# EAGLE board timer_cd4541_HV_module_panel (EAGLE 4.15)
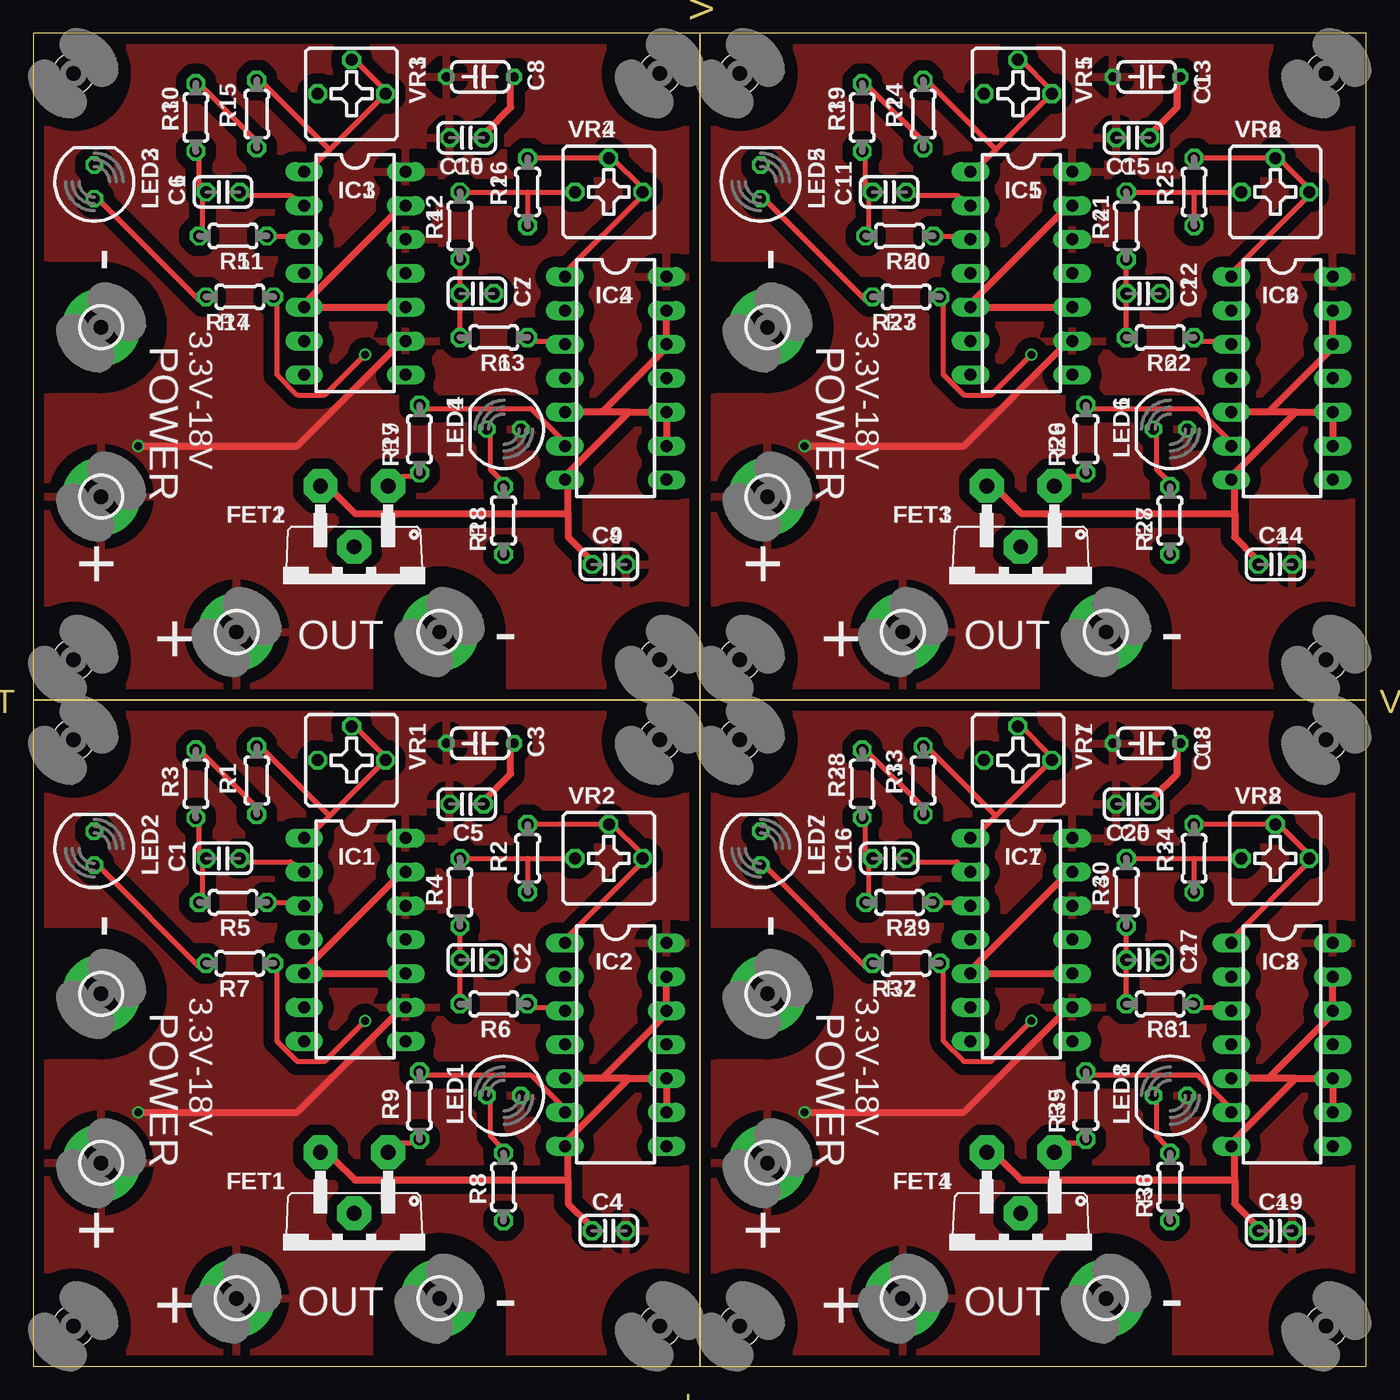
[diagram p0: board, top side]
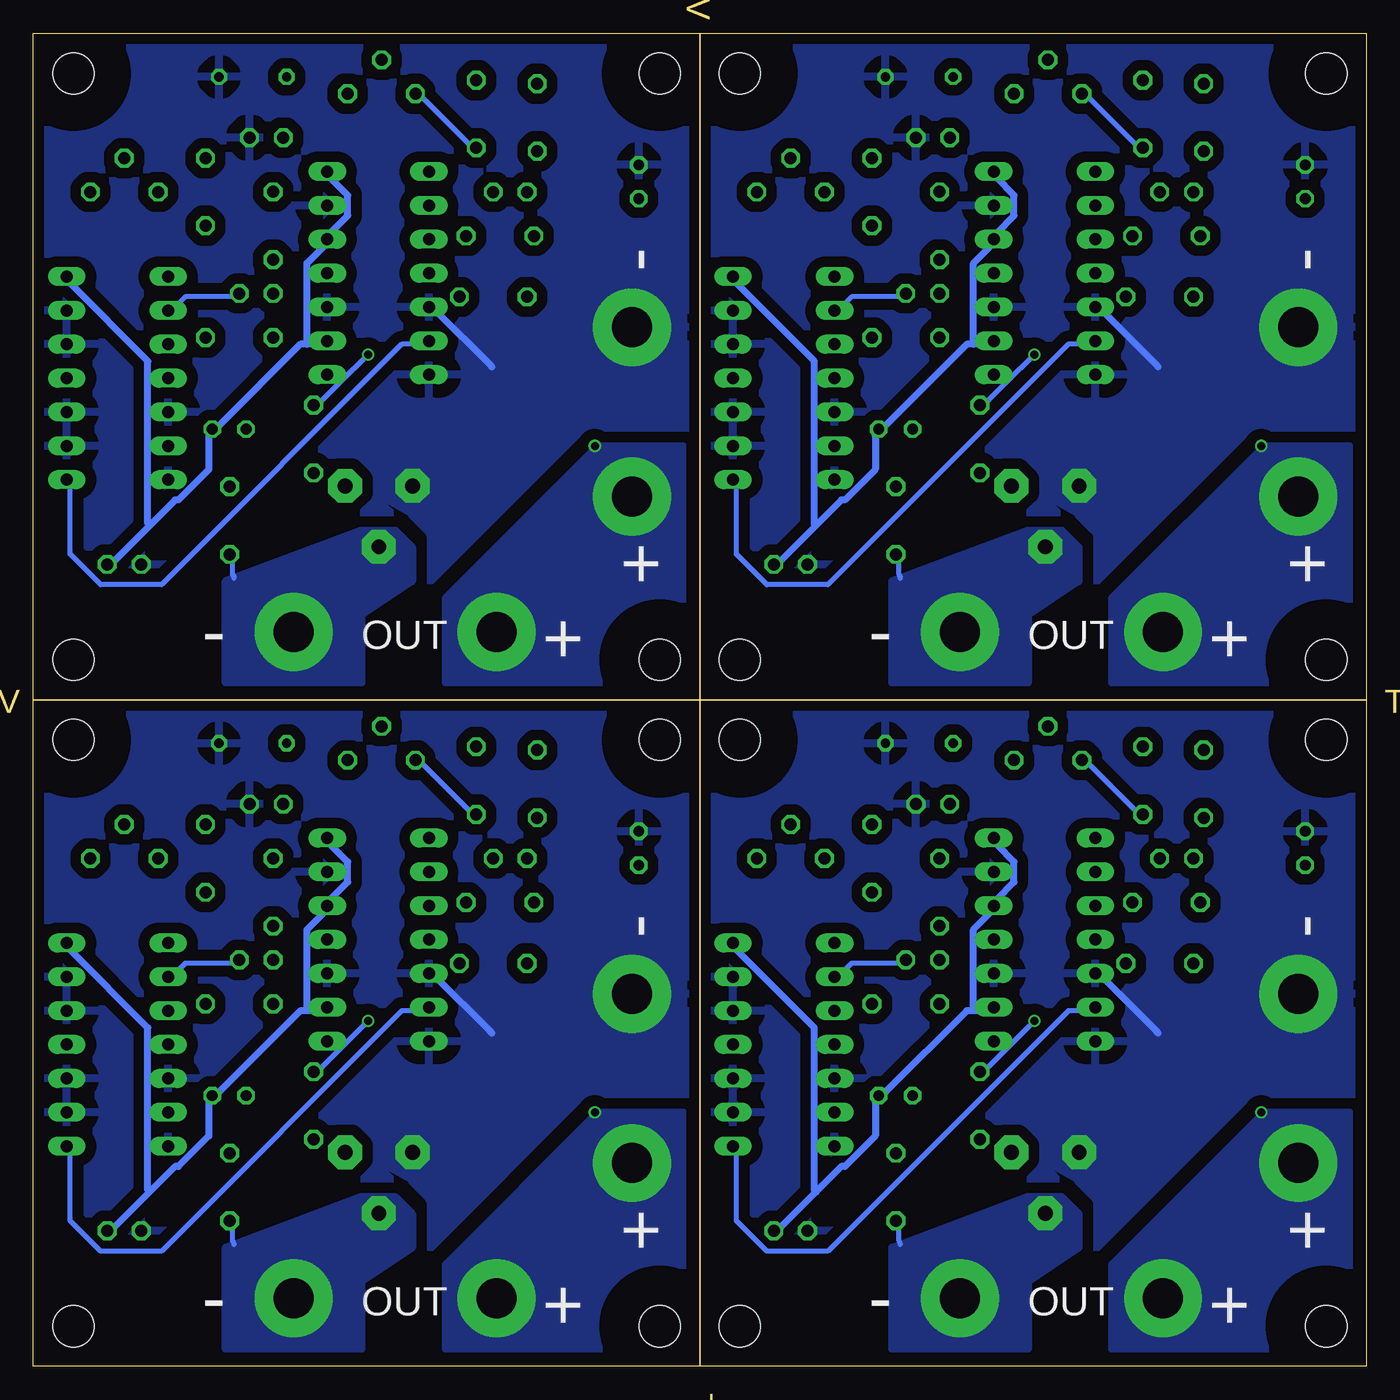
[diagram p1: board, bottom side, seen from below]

Size 100 x 100 mm. Coordinates in mm from the lower left corner, seen from the top.
Outline: 50,0 0,0 0,50
Outline: 50,0 50,50
Outline: 50,50 0,50
Outline: 0,50 50,50
Outline: 50,50 50,100
Outline: 50,100 0,100 0,50
Outline: 50,50 100,50
Outline: 100,50 100,100 50,100
Outline: 50,100 50,50
Outline: 50,0 100,0 100,50
Outline: 100,50 50,50
Outline: 50,50 50,0
Copper layers (1*16): Top 0.035mm / dielectric 1.5mm / Bottom 0.035mm
Design rules "FUSION_IIZUKA_STANDARD": minimum track width 6mil, minimum drill 0.6mm, track to track 8mil, track to pad 8mil, pad to pad 8mil, via to via 8mil, smd to smd 0mil, copper to edge 30mil, drill to drill 10mil, minimum pad ring 10mil, minimum via ring 6mil, stop-mask expansion 2mil, vias tented up to drill 100mil, thermal gap 40mil
Net classes: 0 default: width 0.381 mm, drill 0.406 mm; 1 power: width 0.508 mm, drill 0.508 mm
bKeepout: 20 lines
tRestrict: area 26.7,1 to 34.3,8.9; area 1,24.1 to 8.9,31.8; area 26.7,51 to 34.3,58.9; area 1,74.1 to 8.9,81.8; area 76.7,51 to 84.3,58.9; area 51,74.1 to 58.9,81.8; area 76.7,1 to 84.3,8.9; area 51,24.1 to 58.9,31.8
vRestrict: 1764 lines

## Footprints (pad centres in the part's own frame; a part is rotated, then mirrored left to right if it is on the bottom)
C025-024X044_OLMX = drill 0.9 octagon: 1 -1.27,0; 2 1.27,0
C050-024X044_OLMX = drill 0.7 octagon: 1 -2.54,0; 2 2.54,0
TO-220HV = drill 1.118 pad 2.54 octagon: 1 -2.54,-1.016; 2 0,3.556; 3 2.54,-1.016
3,0-PAD-NOLING = drill 3 pad 5.842 round: B3,0 0,0
3.1-HOLL = hole 3.1: 0,0
DIL14_OLMX = drill 0.9 long: 1 -7.62,-3.81; 2 -5.08,-3.81; 3 -2.54,-3.81; 4 0,-3.81; 5 2.54,-3.81; 6 5.08,-3.81; 7 7.62,-3.81; 8 7.62,3.81; 9 5.08,3.81; 10 2.54,3.81; 11 0,3.81; 12 -2.54,3.81; 13 -5.08,3.81; 14 -7.62,3.81
LED5MM_OLMX = drill 0.8 octagon: A -1.27,0; K 1.27,0
0204/5_OLMX = drill 0.9 octagon: 1 -2.54,0; 2 2.54,0
B25P_OLMX = drill 0.9 octagon: A -2.54,0; E 2.54,0; S 0,2.54

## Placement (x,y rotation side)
C1  1000pF(102)  [C025-024X044_OLMX]  14.22,38.1 0 top
C2  0.01uF(103)  [C025-024X044_OLMX]  33.27,30.48 0 top
C3  10uF  [C050-024X044_OLMX]  33.53,46.74 180 top
C4  0.1uF  [C025-024X044_OLMX]  43.18,10.16 0 top
C5  0.1uF  [C025-024X044_OLMX]  32.51,42.16 180 top
C6  1000pF(102)  [C025-024X044_OLMX]  14.22,88.1 0 top
C7  0.01uF(103)  [C025-024X044_OLMX]  33.27,80.48 0 top
C8  10uF  [C050-024X044_OLMX]  33.53,96.74 180 top
C9  0.1uF  [C025-024X044_OLMX]  43.18,60.16 0 top
C10  0.1uF  [C025-024X044_OLMX]  32.51,92.16 180 top
C11  1000pF(102)  [C025-024X044_OLMX]  64.22,88.1 0 top
C12  0.01uF(103)  [C025-024X044_OLMX]  83.27,80.48 0 top
C13  10uF  [C050-024X044_OLMX]  83.53,96.74 180 top
C14  0.1uF  [C025-024X044_OLMX]  93.18,60.16 0 top
C15  0.1uF  [C025-024X044_OLMX]  82.51,92.16 180 top
C16  1000pF(102)  [C025-024X044_OLMX]  64.22,38.1 0 top
C17  0.01uF(103)  [C025-024X044_OLMX]  83.27,30.48 0 top
C18  10uF  [C050-024X044_OLMX]  83.53,46.74 180 top
C19  0.1uF  [C025-024X044_OLMX]  93.18,10.16 0 top
C20  0.1uF  [C025-024X044_OLMX]  82.51,42.16 180 top
FET1  H7N0308  [TO-220HV]  24.08,15.03 180 top
FET2  H7N0308  [TO-220HV]  24.08,65.03 180 top
FET3  H7N0308  [TO-220HV]  74.08,65.03 180 top
FET4  H7N0308  [TO-220HV]  74.08,15.03 180 top
H1  [3,0-PAD-NOLING]  5.08,15.24 0 top
H2  [3,0-PAD-NOLING]  5.08,27.94 0 top
H3  [3,0-PAD-NOLING]  15.24,5.08 0 top
H4  [3,0-PAD-NOLING]  30.48,5.08 0 top
H5  MOUNT-HOLE3.1  [3.1-HOLL]  3,3 0 top
H6  MOUNT-HOLE3.1  [3.1-HOLL]  47,3 0 top
H7  MOUNT-HOLE3.1  [3.1-HOLL]  3,47 0 top
H8  MOUNT-HOLE3.1  [3.1-HOLL]  47,47 0 top
H9  [3,0-PAD-NOLING]  15.24,55.08 0 top
H10  [3,0-PAD-NOLING]  30.48,55.08 0 top
H11  [3,0-PAD-NOLING]  5.08,65.24 0 top
H12  [3,0-PAD-NOLING]  5.08,77.94 0 top
H13  MOUNT-HOLE3.1  [3.1-HOLL]  3,53 0 top
H14  MOUNT-HOLE3.1  [3.1-HOLL]  47,53 0 top
H15  MOUNT-HOLE3.1  [3.1-HOLL]  3,97 0 top
H16  MOUNT-HOLE3.1  [3.1-HOLL]  47,97 0 top
H17  [3,0-PAD-NOLING]  65.24,55.08 0 top
H18  [3,0-PAD-NOLING]  80.48,55.08 0 top
H19  [3,0-PAD-NOLING]  55.08,65.24 0 top
H20  [3,0-PAD-NOLING]  55.08,77.94 0 top
H21  MOUNT-HOLE3.1  [3.1-HOLL]  53,53 0 top
H22  MOUNT-HOLE3.1  [3.1-HOLL]  97,53 0 top
H23  MOUNT-HOLE3.1  [3.1-HOLL]  53,97 0 top
H24  MOUNT-HOLE3.1  [3.1-HOLL]  97,97 0 top
H25  [3,0-PAD-NOLING]  65.24,5.08 0 top
H26  [3,0-PAD-NOLING]  80.48,5.08 0 top
H27  [3,0-PAD-NOLING]  55.08,15.24 0 top
H28  [3,0-PAD-NOLING]  55.08,27.94 0 top
H29  MOUNT-HOLE3.1  [3.1-HOLL]  53,3 0 top
H30  MOUNT-HOLE3.1  [3.1-HOLL]  97,3 0 top
H31  MOUNT-HOLE3.1  [3.1-HOLL]  53,47 0 top
H32  MOUNT-HOLE3.1  [3.1-HOLL]  97,47 0 top
IC1  CD4541  [DIL14_OLMX]  24.13,32 270 top
IC2  CD4541  [DIL14_OLMX]  43.69,24.13 270 top
IC3  CD4541  [DIL14_OLMX]  24.13,82 270 top
IC4  CD4541  [DIL14_OLMX]  43.69,74.13 270 top
IC5  CD4541  [DIL14_OLMX]  74.13,82 270 top
IC6  CD4541  [DIL14_OLMX]  93.69,74.13 270 top
IC7  CD4541  [DIL14_OLMX]  74.13,32 270 top
IC8  CD4541  [DIL14_OLMX]  93.69,24.13 270 top
LED1  [LED5MM_OLMX]  35.31,20.3 180 top
LED2  [LED5MM_OLMX]  4.57,38.86 90 top
LED3  [LED5MM_OLMX]  4.57,88.86 90 top
LED4  [LED5MM_OLMX]  35.31,70.3 180 top
LED5  [LED5MM_OLMX]  54.57,88.86 90 top
LED6  [LED5MM_OLMX]  85.31,70.3 180 top
LED7  [LED5MM_OLMX]  54.57,38.86 90 top
LED8  [LED5MM_OLMX]  85.31,20.3 180 top
R1  [0204/5_OLMX]  16.76,43.94 90 top
R2  [0204/5_OLMX]  37.08,38.1 90 top
R3  5.1k  [0204/5_OLMX]  12.19,43.69 90 top
R4  7.5k  [0204/5_OLMX]  32,35.56 90 top
R5  22k  [0204/5_OLMX]  14.99,34.8 0 top
R6  22k  [0204/5_OLMX]  34.54,27.18 0 top
R7  1k  [0204/5_OLMX]  15.49,30.23 180 top
R8  1k  [0204/5_OLMX]  35.27,13.45 270 top
R9  100  [0204/5_OLMX]  28.97,19.56 270 top
R10  5.1k  [0204/5_OLMX]  12.19,93.69 90 top
R11  22k  [0204/5_OLMX]  14.99,84.8 0 top
R12  7.5k  [0204/5_OLMX]  32,85.56 90 top
R13  22k  [0204/5_OLMX]  34.54,77.18 0 top
R14  1k  [0204/5_OLMX]  15.49,80.23 180 top
R15  [0204/5_OLMX]  16.76,93.94 90 top
R16  [0204/5_OLMX]  37.08,88.1 90 top
R17  100  [0204/5_OLMX]  28.97,69.56 270 top
R18  1k  [0204/5_OLMX]  35.27,63.45 270 top
R19  5.1k  [0204/5_OLMX]  62.19,93.69 90 top
R20  22k  [0204/5_OLMX]  64.99,84.8 0 top
R21  7.5k  [0204/5_OLMX]  82,85.56 90 top
R22  22k  [0204/5_OLMX]  84.54,77.18 0 top
R23  1k  [0204/5_OLMX]  65.49,80.23 180 top
R24  [0204/5_OLMX]  66.76,93.94 90 top
R25  [0204/5_OLMX]  87.08,88.1 90 top
R26  100  [0204/5_OLMX]  78.97,69.56 270 top
R27  1k  [0204/5_OLMX]  85.27,63.45 270 top
R28  5.1k  [0204/5_OLMX]  62.19,43.69 90 top
R29  22k  [0204/5_OLMX]  64.99,34.8 0 top
R30  7.5k  [0204/5_OLMX]  82,35.56 90 top
R31  22k  [0204/5_OLMX]  84.54,27.18 0 top
R32  1k  [0204/5_OLMX]  65.49,30.23 180 top
R33  [0204/5_OLMX]  66.76,43.94 90 top
R34  [0204/5_OLMX]  87.08,38.1 90 top
R35  100  [0204/5_OLMX]  78.97,19.56 270 top
R36  1k  [0204/5_OLMX]  85.27,13.45 270 top
VR1  10k  [B25P_OLMX]  23.88,45.47 0 top
VR2  10k  [B25P_OLMX]  43.18,38.1 0 top
VR3  10k  [B25P_OLMX]  23.88,95.47 0 top
VR4  10k  [B25P_OLMX]  43.18,88.1 0 top
VR5  10k  [B25P_OLMX]  73.88,95.47 0 top
VR6  10k  [B25P_OLMX]  93.18,88.1 0 top
VR7  10k  [B25P_OLMX]  73.88,45.47 0 top
VR8  10k  [B25P_OLMX]  93.18,38.1 0 top

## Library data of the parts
C1-C20 R1-R36 = rcl
FET1-FET4 = transistor-power
H1-H32 = holes
IC1-IC8 = 001mylib
LED1-LED8 = led
VR1-VR8 = pot

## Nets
GND [power]: C3.1 C4.1 C5.1 FET1.3 H2.B3,0 IC1.5 IC1.7 IC1.10 IC1.13 IC2.5 IC2.7 IC2.9 IC2.10 IC2.12 IC2.13 LED2.K
GND1 [power]: C8.1 C9.1 C10.1 FET2.3 H12.B3,0 IC3.5 IC3.7 IC3.10 IC3.13 IC4.5 IC4.7 IC4.9 IC4.10 IC4.12 IC4.13 LED3.K
GND2 [power]: C13.1 C14.1 C15.1 FET3.3 H20.B3,0 IC5.5 IC5.7 IC5.10 IC5.13 IC6.5 IC6.7 IC6.9 IC6.10 IC6.12 IC6.13 LED5.K
GND3 [power]: C18.1 C19.1 C20.1 FET4.3 H28.B3,0 IC7.5 IC7.7 IC7.10 IC7.13 IC8.5 IC8.7 IC8.9 IC8.10 IC8.12 IC8.13 LED7.K
N$1: IC2.1 R2.2 VR2.E VR2.S
N$2: C1.1 R3.1 R5.1
N$3: IC1.6 IC2.8
N$4: C2.1 R4.1 R6.1
N$5: IC1.1 R1.2 VR1.E VR1.S
N$6: C1.2 IC1.2
N$7: LED1.K R8.1
N$8: IC3.1 R15.2 VR3.E VR3.S
N$9: LED2.A R7.2
N$10: IC1.3 R5.2
N$11: R2.1 R4.2 VR2.A
N$12: C6.2 IC3.2
N$13: R1.1 R3.2 VR1.A
N$14: IC3.3 R11.2
N$15: C7.2 IC4.2
N$16: IC4.3 R13.2
N$17: IC3.8 IC4.6 R14.1 R17.1
N$18: C6.1 R10.1 R11.1
N$19: FET1.1 R9.2
N$20: C2.2 IC2.2
N$21: IC2.3 R6.2
N$22: IC1.8 IC2.6 R7.1 R9.1
N$23: C7.1 R12.1 R13.1
N$24: IC3.6 IC4.8
N$25: IC4.1 R16.2 VR4.E VR4.S
N$26: R10.2 R15.1 VR3.A
N$27: R12.2 R16.1 VR4.A
N$28: LED3.A R14.2
N$29: FET2.1 R17.2
N$30: LED4.K R18.1
N$31: IC5.1 R24.2 VR5.E VR5.S
N$32: C11.2 IC5.2
N$33: IC5.3 R20.2
N$34: C12.2 IC6.2
N$35: IC6.3 R22.2
N$36: IC5.8 IC6.6 R23.1 R26.1
N$37: C11.1 R19.1 R20.1
N$38: C12.1 R21.1 R22.1
N$39: IC5.6 IC6.8
N$40: IC6.1 R25.2 VR6.E VR6.S
N$41: R19.2 R24.1 VR5.A
N$42: R21.2 R25.1 VR6.A
N$43: LED5.A R23.2
N$44: FET3.1 R26.2
N$45: LED6.K R27.1
N$46: IC7.1 R33.2 VR7.E VR7.S
N$47: C16.2 IC7.2
N$48: IC7.3 R29.2
N$49: C17.2 IC8.2
N$50: IC8.3 R31.2
N$51: IC7.8 IC8.6 R32.1 R35.1
N$52: C16.1 R28.1 R29.1
N$53: C17.1 R30.1 R31.1
N$54: IC7.6 IC8.8
N$55: IC8.1 R34.2 VR8.E VR8.S
N$56: R28.2 R33.1 VR7.A
N$57: R30.2 R34.1 VR8.A
N$58: LED7.A R32.2
N$59: FET4.1 R35.2
N$60: LED8.K R36.1
OUT-: FET1.2 H4.B3,0 R8.2
OUT-1: FET2.2 H10.B3,0 R18.2
OUT-2: FET3.2 H18.B3,0 R27.2
OUT-3: FET4.2 H26.B3,0 R36.2
VCC [power]: C3.2 C4.2 C5.2 H1.B3,0 H3.B3,0 IC1.9 IC1.12 IC1.14 IC2.14 LED1.A
VCC1 [power]: C8.2 C9.2 C10.2 H9.B3,0 H11.B3,0 IC3.9 IC3.12 IC3.14 IC4.14 LED4.A
VCC2 [power]: C13.2 C14.2 C15.2 H17.B3,0 H19.B3,0 IC5.9 IC5.12 IC5.14 IC6.14 LED6.A
VCC3 [power]: C18.2 C19.2 C20.2 H25.B3,0 H27.B3,0 IC7.9 IC7.12 IC7.14 IC8.14 LED8.A

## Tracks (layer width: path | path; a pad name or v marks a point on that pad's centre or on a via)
GND
  Top 0.508: 40.13,13.97 40.13,12.19 41.66,10.67 C4.1 | 40.13,13.97 40.13,16 IC2.7 40.13,17.02 44.7,21.59 | IC2.13 IC2.12 47.24,26.16 42.67,21.59 | 44.7,21.59 42.67,21.59 | 42.67,21.59 IC2.5 | 44.7,21.59 IC2.10 IC2.9 | C3.1 35.81,46.23 35.81,44.45 34.04,42.67 C5.1 | IC1.10 IC1.5 20.57,29.97 27.43,36.83 IC1.13 | 40.13,13.97 24.13,13.97 22.61,15.49 FET1.3
  Bottom 0.508: IC1.5 19.81,29.21 15.75,25.15 15.6,24.97
  pour Bottom (isolate 0.813, rank 2): 0,50 50,50 50,0 0,0
  pour Bottom (isolate 0.813, no thermals): 1.27,33.02 1.27,22.86 6.35,22.86 20.32,13.97 21.59,13.97 23.86,15.24 23.86,17.78 6.35,33.02
GND1
  Top 0.508: 40.13,63.97 40.13,62.19 41.66,60.67 C9.1 | 40.13,63.97 40.13,66 IC4.7 40.13,67.02 44.7,71.59 | IC4.13 IC4.12 47.24,76.16 42.67,71.59 | 44.7,71.59 42.67,71.59 | 42.67,71.59 IC4.5 | 44.7,71.59 IC4.10 IC4.9 | C8.1 35.81,96.23 35.81,94.45 34.04,92.67 C10.1 | IC3.10 IC3.5 20.57,79.97 27.43,86.83 IC3.13 | 40.13,63.97 24.13,63.97 22.61,65.49 FET2.3
  Bottom 0.508: IC3.5 19.81,79.21 15.75,75.15 15.6,74.97
  pour Bottom (isolate 0.813, rank 2): 0,100 50,100 50,50 0,50
  pour Bottom (isolate 0.813, no thermals): 1.27,83.02 1.27,72.86 6.35,72.86 20.32,63.97 21.59,63.97 23.86,65.24 23.86,67.78 6.35,83.02
GND2
  Top 0.508: 90.13,63.97 90.13,62.19 91.66,60.67 C14.1 | 90.13,63.97 90.13,66 IC6.7 90.13,67.02 94.7,71.59 | IC6.13 IC6.12 97.24,76.16 92.67,71.59 | 94.7,71.59 92.67,71.59 | 92.67,71.59 IC6.5 | 94.7,71.59 IC6.10 IC6.9 | C13.1 85.81,96.23 85.81,94.45 84.04,92.67 C15.1 | IC5.10 IC5.5 70.57,79.97 77.43,86.83 IC5.13 | 90.13,63.97 74.13,63.97 72.61,65.49 FET3.3
  Bottom 0.508: IC5.5 69.81,79.21 65.75,75.15 65.6,74.97
  pour Bottom (isolate 0.813, rank 2): 50,100 100,100 100,50 50,50
  pour Bottom (isolate 0.813, no thermals): 51.27,83.02 51.27,72.86 56.35,72.86 70.32,63.97 71.59,63.97 73.86,65.24 73.86,67.78 56.35,83.02
GND3
  Top 0.508: 90.13,13.97 90.13,12.19 91.66,10.67 C19.1 | 90.13,13.97 90.13,16 IC8.7 90.13,17.02 94.7,21.59 | IC8.13 IC8.12 97.24,26.16 92.67,21.59 | 94.7,21.59 92.67,21.59 | 92.67,21.59 IC8.5 | 94.7,21.59 IC8.10 IC8.9 | C18.1 85.81,46.23 85.81,44.45 84.04,42.67 C20.1 | IC7.10 IC7.5 70.57,29.97 77.43,36.83 IC7.13 | 90.13,13.97 74.13,13.97 72.61,15.49 FET4.3
  Bottom 0.508: IC7.5 69.81,29.21 65.75,25.15 65.6,24.97
  pour Bottom (isolate 0.813, rank 2): 50,50 100,50 100,0 50,0
  pour Bottom (isolate 0.813, no thermals): 51.27,33.02 51.27,22.86 56.35,22.86 70.32,13.97 71.59,13.97 73.86,15.24 73.86,17.78 56.35,33.02
N$1
  Top 0.381: R2.2 VR2.S 43.69,40.39 45.47,38.61 VR2.E 45.47,37.59 40.13,32.26 IC2.1
N$2
  Top 0.381: R5.1 12.7,35.31 12.7,37.59 C1.1 12.45,38.35 12.45,40.64 R3.1
N$3
  Bottom 0.381: IC1.6 20.83,26.67 22.35,26.67 40.39,8.64 44.96,8.64 47.24,10.92 47.24,16 IC2.8
N$4
  Top 0.381: R6.1 C2.1 R4.1
N$5
  Top 0.381: 22.23,41.27 20.83,39.88 IC1.1 | 22.23,41.27 VR1.E 26.16,45.97 24.38,47.75 VR1.S | R1.2 17.27,46.23 22.23,41.27
N$6
  Top 0.381: C1.2 16,37.85 19.3,37.85 19.81,37.34 IC1.2
N$7
  Top 0.381: LED1.K 34.29,19.81 34.29,17.27 35.05,16.51 R8.1
N$8
  Top 0.381: 22.23,91.28 20.83,89.88 IC3.1 | 22.23,91.28 VR3.E 26.16,95.97 24.38,97.75 VR3.S | R15.2 17.27,96.23 22.23,91.28
N$9
  Top 0.381: LED2.A 5.08,37.34 12.45,29.97 R7.2
N$10
  Top 0.381: R5.2 19.81,34.8 IC1.3
N$11
  Top 0.381: R4.2 37.08,38.1 | 37.08,38.1 VR2.A | 37.08,38.1 R2.1
N$12
  Top 0.381: C6.2 16,87.85 19.3,87.85 19.81,87.34 IC3.2
N$13
  Top 0.381: R3.2 12.7,45.97 16.76,41.91 R1.1
  Bottom 0.381: R1.1 17.27,41.66 20.83,45.21 VR1.A
N$14
  Top 0.381: R11.2 19.81,84.8 IC3.3
N$15
  Bottom 0.381: C7.2 35.05,80.23 38.61,80.23 39.37,79.46 IC4.2
N$16
  Top 0.381: R13.2 37.59,76.92 39.37,76.92 IC4.3
N$17  (via drill 0.6)
  Top 0.381: v24.89,75.91 21.84,72.86 19.81,72.86 18.29,74.38 18.29,79.72 R14.1 | IC4.6 39.62,69.56 37.34,71.84 29.46,71.84 R17.1
  Bottom 0.381: 27.05,73.75 28.45,72.35 R17.1 | v24.89,75.91 27.05,73.75 | IC3.8 27.43,74.13 27.05,73.75
N$18
  Top 0.381: R11.1 12.7,85.31 12.7,87.59 C6.1 12.45,88.35 12.45,90.64 R10.1
N$19
  Top 0.381: R9.2 28.45,16.76 27.69,16.76 FET1.1
N$20
  Bottom 0.381: C2.2 35.05,30.23 38.61,30.23 39.37,29.46 IC2.2
N$21
  Top 0.381: R6.2 37.59,26.92 39.37,26.92 IC2.3
N$22  (via drill 0.6)
  Top 0.381: v24.89,25.91 21.84,22.86 19.81,22.86 18.29,24.38 18.29,29.72 R7.1 | IC2.6 39.62,19.56 37.34,21.84 29.46,21.84 R9.1
  Bottom 0.381: 27.05,23.75 28.45,22.35 R9.1 | v24.89,25.91 27.05,23.75 | IC1.8 27.43,24.13 27.05,23.75
N$23
  Top 0.381: R13.1 C7.1 R12.1
N$24
  Bottom 0.381: IC3.6 20.83,76.67 22.35,76.67 40.39,58.64 44.96,58.64 47.24,60.92 47.24,66 IC4.8
N$25
  Top 0.381: R16.2 VR4.S 43.69,90.39 45.47,88.61 VR4.E 45.47,87.59 40.13,82.26 IC4.1
N$26
  Top 0.381: R10.2 12.7,95.97 16.76,91.91 R15.1
  Bottom 0.381: R15.1 17.27,91.66 20.83,95.21 VR3.A
N$27
  Top 0.381: R12.2 37.08,88.1 | 37.08,88.1 VR4.A | 37.08,88.1 R16.1
N$28
  Top 0.381: LED3.A 5.08,87.34 12.45,79.97 R14.2
N$29
  Top 0.381: R17.2 28.45,66.76 27.69,66.76 FET2.1
N$30
  Top 0.381: LED4.K 34.29,69.81 34.29,67.27 35.05,66.51 R18.1
N$31
  Top 0.381: 72.22,91.28 70.83,89.88 IC5.1 | 72.22,91.28 VR5.E 76.16,95.97 74.38,97.75 VR5.S | R24.2 67.27,96.23 72.22,91.28
N$32
  Top 0.381: C11.2 66,87.85 69.3,87.85 69.81,87.34 IC5.2
N$33
  Top 0.381: R20.2 69.81,84.8 IC5.3
N$34
  Bottom 0.381: C12.2 85.05,80.23 88.61,80.23 89.37,79.46 IC6.2
N$35
  Top 0.381: R22.2 87.59,76.92 89.37,76.92 IC6.3
N$36  (via drill 0.6)
  Top 0.381: v74.89,75.91 71.84,72.86 69.81,72.86 68.29,74.38 68.29,79.72 R23.1 | IC6.6 89.62,69.56 87.34,71.84 79.46,71.84 R26.1
  Bottom 0.381: 77.05,73.75 78.45,72.35 R26.1 | v74.89,75.91 77.05,73.75 | IC5.8 77.43,74.13 77.05,73.75
N$37
  Top 0.381: R20.1 62.7,85.31 62.7,87.59 C11.1 62.45,88.35 62.45,90.64 R19.1
N$38
  Top 0.381: R22.1 C12.1 R21.1
N$39
  Bottom 0.381: IC5.6 70.83,76.67 72.35,76.67 90.39,58.64 94.96,58.64 97.24,60.92 97.24,66 IC6.8
N$40
  Top 0.381: R25.2 VR6.S 93.69,90.39 95.47,88.61 VR6.E 95.47,87.59 90.13,82.26 IC6.1
N$41
  Top 0.381: R19.2 62.7,95.97 66.76,91.91 R24.1
  Bottom 0.381: R24.1 67.27,91.66 70.83,95.21 VR5.A
N$42
  Top 0.381: R21.2 87.08,88.1 | 87.08,88.1 VR6.A | 87.08,88.1 R25.1
N$43
  Top 0.381: LED5.A 55.08,87.34 62.45,79.97 R23.2
N$44
  Top 0.381: R26.2 78.45,66.76 77.69,66.76 FET3.1
N$45
  Top 0.381: LED6.K 84.29,69.81 84.29,67.27 85.05,66.51 R27.1
N$46
  Top 0.381: 72.22,41.27 70.83,39.88 IC7.1 | 72.22,41.27 VR7.E 76.16,45.97 74.38,47.75 VR7.S | R33.2 67.27,46.23 72.22,41.27
N$47
  Top 0.381: C16.2 66,37.85 69.3,37.85 69.81,37.34 IC7.2
N$48
  Top 0.381: R29.2 69.81,34.8 IC7.3
N$49
  Bottom 0.381: C17.2 85.05,30.23 88.61,30.23 89.37,29.46 IC8.2
N$50
  Top 0.381: R31.2 87.59,26.92 89.37,26.92 IC8.3
N$51  (via drill 0.6)
  Top 0.381: v74.89,25.91 71.84,22.86 69.81,22.86 68.29,24.38 68.29,29.72 R32.1 | IC8.6 89.62,19.56 87.34,21.84 79.46,21.84 R35.1
  Bottom 0.381: 77.05,23.75 78.45,22.35 R35.1 | v74.89,25.91 77.05,23.75 | IC7.8 77.43,24.13 77.05,23.75
N$52
  Top 0.381: R29.1 62.7,35.31 62.7,37.59 C16.1 62.45,38.35 62.45,40.64 R28.1
N$53
  Top 0.381: R31.1 C17.1 R30.1
N$54
  Bottom 0.381: IC7.6 70.83,26.67 72.35,26.67 90.39,8.64 94.96,8.64 97.24,10.92 97.24,16 IC8.8
N$55
  Top 0.381: R34.2 VR8.S 93.69,40.39 95.47,38.61 VR8.E 95.47,37.59 90.13,32.26 IC8.1
N$56
  Top 0.381: R28.2 62.7,45.97 66.76,41.91 R33.1
  Bottom 0.381: R33.1 67.27,41.66 70.83,45.21 VR7.A
N$57
  Top 0.381: R30.2 87.08,38.1 | 87.08,38.1 VR8.A | 87.08,38.1 R34.1
N$58
  Top 0.381: LED7.A 55.08,37.34 62.45,29.97 R32.2
N$59
  Top 0.381: R35.2 78.45,16.76 77.69,16.76 FET4.1
N$60
  Top 0.381: LED8.K 84.29,19.81 84.29,17.27 85.05,16.51 R36.1
OUT-
  Bottom 0.381: R8.2 35.05,10.41 35.05,9.4 34.95,9.12
  pour Bottom (isolate 1.016, no thermals): 25.4,1.27 35.56,1.27 35.56,8.89 25.4,12.7 22.86,12.7 21.59,11.43 21.59,8.89 25.4,6.35
OUT-1
  Bottom 0.381: R18.2 35.05,60.41 35.05,59.4 34.95,59.12
  pour Bottom (isolate 1.016, no thermals): 25.4,51.27 35.56,51.27 35.56,58.89 25.4,62.7 22.86,62.7 21.59,61.43 21.59,58.89 25.4,56.35
OUT-2
  Bottom 0.381: R27.2 85.05,60.41 85.05,59.4 84.95,59.12
  pour Bottom (isolate 1.016, no thermals): 75.4,51.27 85.56,51.27 85.56,58.89 75.4,62.7 72.86,62.7 71.59,61.43 71.59,58.89 75.4,56.35
OUT-3
  Bottom 0.381: R36.2 85.05,10.41 85.05,9.4 84.95,9.12
  pour Bottom (isolate 1.016, no thermals): 75.4,1.27 85.56,1.27 85.56,8.89 75.4,12.7 72.86,12.7 71.59,11.43 71.59,8.89 75.4,6.35
VCC  (via drill 0.6)
  Top 0.508: v7.87,19.05 19.81,19.05 27.43,26.67 IC1.9
  Bottom 0.508: 29.46,26.67 28.45,26.67 IC1.9 | 29.46,26.67 29.97,26.67 36.07,20.57 LED1.A 36.83,19.81 36.83,17.27 39.12,14.99 39.37,14.99 41.27,13.08 | 41.27,13.08 43.94,10.41 C4.2 | IC2.14 47.24,31.24 41.4,25.4 41.4,13.21 41.27,13.08 | 29.46,26.67 29.46,32.77 28.19,34.04 IC1.12 27.69,35.05 26.42,36.32 26.42,37.85 27.69,39.12 IC1.14 | v7.87,19.05 7.75,18.92
  pour Top (isolate 0.813, rank 2): 0,50 50,50 50,0 0,0
  pour Bottom (isolate 1.016, no thermals): 1.27,19.05 1.27,1.27 19.05,1.27 19.05,7.62 7.62,19.05
VCC1  (via drill 0.6)
  Top 0.508: v7.87,69.05 19.81,69.05 27.43,76.67 IC3.9
  Bottom 0.508: 29.46,76.67 28.45,76.67 IC3.9 | 29.46,76.67 29.97,76.67 36.07,70.57 LED4.A 36.83,69.81 36.83,67.27 39.12,64.99 39.37,64.99 41.27,63.08 | 41.27,63.08 43.94,60.41 C9.2 | IC4.14 47.24,81.24 41.4,75.4 41.4,63.21 41.27,63.08 | 29.46,76.67 29.46,82.77 28.19,84.04 IC3.12 27.69,85.05 26.42,86.32 26.42,87.85 27.69,89.12 IC3.14 | v7.87,69.05 7.75,68.92
  pour Top (isolate 0.813, rank 2): 0,100 50,100 50,50 0,50
  pour Bottom (isolate 1.016, no thermals): 1.27,69.05 1.27,51.27 19.05,51.27 19.05,57.62 7.62,69.05
VCC2  (via drill 0.6)
  Top 0.508: v57.87,69.05 69.81,69.05 77.43,76.67 IC5.9
  Bottom 0.508: 79.46,76.67 78.45,76.67 IC5.9 | 79.46,76.67 79.97,76.67 86.07,70.57 LED6.A 86.83,69.81 86.83,67.27 89.12,64.99 89.37,64.99 91.28,63.08 | 91.28,63.08 93.94,60.41 C14.2 | IC6.14 97.24,81.24 91.4,75.4 91.4,63.21 91.28,63.08 | 79.46,76.67 79.46,82.77 78.19,84.04 IC5.12 77.69,85.05 76.42,86.32 76.42,87.85 77.69,89.12 IC5.14 | v57.87,69.05 57.75,68.92
  pour Top (isolate 0.813, rank 2): 50,100 100,100 100,50 50,50
  pour Bottom (isolate 1.016, no thermals): 51.27,69.05 51.27,51.27 69.05,51.27 69.05,57.62 57.62,69.05
VCC3  (via drill 0.6)
  Top 0.508: v57.87,19.05 69.81,19.05 77.43,26.67 IC7.9
  Bottom 0.508: 79.46,26.67 78.45,26.67 IC7.9 | 79.46,26.67 79.97,26.67 86.07,20.57 LED8.A 86.83,19.81 86.83,17.27 89.12,14.99 89.37,14.99 91.28,13.08 | 91.28,13.08 93.94,10.41 C19.2 | IC8.14 97.24,31.24 91.4,25.4 91.4,13.21 91.28,13.08 | 79.46,26.67 79.46,32.77 78.19,34.04 IC7.12 77.69,35.05 76.42,36.32 76.42,37.85 77.69,39.12 IC7.14 | v57.87,19.05 57.75,18.92
  pour Top (isolate 0.813, rank 2): 50,50 100,50 100,0 50,0
  pour Bottom (isolate 1.016, no thermals): 51.27,19.05 51.27,1.27 69.05,1.27 69.05,7.62 57.62,19.05

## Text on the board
Dimension: V-CUT | V-CUT | V-CUT | V-CUT
tPlace: - | - | 3.3V-18V | 3.3V-18V | POWER | POWER | + | + | OUT | OUT | + | - | + | - | - | - | 3.3V-18V | 3.3V-18V | POWER | POWER | + | + | OUT | OUT | + | - | + | -
bPlace: - | - | + | + | OUT | OUT | + | - | + | - | - | - | + | + | OUT | OUT | + | - | + | -
_tNames: VR1 | C3 | VR1 | C3 | R3 | R1 | R3 | R1 | VR2 | VR2 | LED2 | C5 | LED2 | C5 | IC1 | IC1 | C1 | R2 | C1 | R2 | R4 | R4 | R5 | R5 | IC2 | IC2 | R7 | C2 | R7 | C2 | R6 | R6 | LED1 | LED1 | R9 | R9 | FET1 | FET1 | R8 | R8 | C4 | C4 | VR1 | C3 | VR1 | C3 | R3 | R1 | R3 | R1 | VR2 | VR2 | LED2 | C5 | LED2 | C5 | IC1 | IC1 | C1 | R2 | C1 | R2 | R4 | R4 | R5 | R5 | IC2 | IC2 | R7 | C2 | R7 | C2 | R6 | R6 | LED1 | LED1 | R9 | R9 | FET1 | FET1 | R8 | R8 | C4 | C4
